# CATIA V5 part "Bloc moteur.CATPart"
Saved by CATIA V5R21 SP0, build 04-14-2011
Part number: bloc moteur
Material "Aluminium": density 2710 kg/m3, Young's modulus 7e+10 Pa, Poisson ratio 0.346, thermal expansion 2.36e-05 1/K
Bounding box of the stored display mesh (mm): x -34 to 34, y -31.5 to 37.5, z -15.714 to 54
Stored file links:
  C:\Users\Olivier\Desktop\redaction CATIA (local)\CATIA\DONNEES\Exercice mise en plan 2 (Pompe de ventilation)\Pompe de ventilation (Product inclus)\Bloc moteur.CATPart
  C:\Program Files\Dassault Systemes\B21\win_b64\startup\materials\French\Catalog.CATMaterial
  C:\Users\Olivier\Desktop\redaction CATIA (local)\CATIA\DONNEES\Exercice mise en plan 2 (Pompe de ventilation)\Pompe de ventilation (Product inclus)\CATIA_EnvironmentMap_Satin_512x512.jpg
  C:\Users\Olivier\Desktop\redaction CATIA (local)\pompe à moteur de ventilation refait\Pompe_a_moteur_de_ventilation.CATProduct
  C:\Users\Olivier\Desktop\redaction CATIA (local)\pompe à moteur de ventilation refait\Ecrou a collerette M5.CATPart
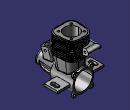
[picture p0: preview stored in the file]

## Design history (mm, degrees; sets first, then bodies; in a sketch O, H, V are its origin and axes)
Body1 (main body), material "Aluminium"
  Sketch1 on yz-plane, origin (0, 0, 0), H (0, 1, 0), V (0, 0, 1)
    line L1 (30, 0) -> (30, -15.5)
    line L2 (30, -15.5) -> (-3.0173, -15.5)
    line L3 (30, 0) -> (-30, 0)
    point P3 (-30, 0)
    line L4 (-30, -9) -> (-6, -11.039)
    point P4 (-30, -9)
    point P5 (-6, -11.039)
    line L5 (-6, -11.039) -> (-3.0173, -15.5)
    line L6 (-30, 0) -> (-30, -9)
    distance P3 P4 = 9
    distance P5 L1 = 36
    length L3 = 60
    length L1 = 15.5
    vertical: L1 V, L6 V
    horizontal: L2 H, L3 H
  Shaft1: profile Sketch1, axis Sketch1.L3, angle 360
  Plane1: type Offset, RefPlane xy-plane, Offset 54
  Sketch2 on Plane1, origin (0, 0, 54), H (1, 0, 0), V (0, 1, 0)
    point P1 (-15.991, -3)
    line L1 (-7.4607, -3) -> (7.4737, -3)
    line L2 (4.6271, 28) -> (-4.6217, 28)
    point P2 (16.009, -3)
    point P3 (14, 28)
    point P4 (-14, 28)
    reference projected line E1 (15.5, 30) -> (-15.5, 30) from edge [face of Shaft1 from Sketch1.L1 | face of Shaft1 from Sketch1.L2]
    line L3 (15.457, 5.5174) -> (14.6061, 18.6467)
    line L4 (-15.4443, 5.5128) -> (-14.6011, 18.6409)
    arc A1 centre (-7.4607, 5) radius 8 from (-7.4607, -3) to (-15.4443, 5.5128) cw
    arc A2 centre (7.4737, 5) radius 8 from (7.4737, -3) to (15.457, 5.5174) ccw
    arc A3 centre (4.6271, 18) radius 10 from (14.6061, 18.6467) to (4.6271, 28) ccw
    arc A4 centre (-4.6217, 18) radius 10 from (-4.6217, 28) to (-14.6011, 18.6409) ccw
    distance E1 L2 = 2
    distance P4 V = 14
    distance P1 P2 = 32
    radius A1 = 8
    radius A2 = 8
    distance P3 P4 = 28
    radius A3 = 10
    radius A4 = 10
    distance L1 L2 = 31
    horizontal: L2 H
    coincidence: L1 P1, L4 P1, L1 P2, L3 P2, L3 P3, L2 P3, L2 P4, L4 P4
    tangency: A1 L1, A1 L4, A2 L1, A2 L3, A3 L3, A3 L2, A4 L2, A4 L4
  Pad1: profile Sketch2, direction (0, 0, -1), length 27
  Sketch3 on end face of Pad1, origin (0, 0, 27), H (1, 0, 0), V (0, -1, 0)
  Sketch4 on end face of Pad1, origin (0, 0, 27), H (1, 0, 0), V (0, -1, 0)
    construction line L1 through (0, 0) direction (1, 0)
    construction line L2 through (0, 0) direction (0, 1)
  Sketch5 on end face of Pad1, origin (0, 0, 27), H (1, 0, 0), V (0, -1, 0)
    reference projected arc E1 centre (-4.6217, -18) radius 10 from (-14.6011, -18.6409) to (-4.6217, -28) ccw from edge [end face of Pad1 | face of Pad1 from Sketch2.A4]
    reference projected arc E2 centre (-7.4607, -5) radius 8 from (-7.4607, 3) to (-15.4443, -5.5128) ccw from edge [end face of Pad1 | face of Pad1 from Sketch2.A1]
    reference projected arc E3 centre (4.6271, -18) radius 10 from (4.6271, -28) to (14.6061, -18.6467) ccw from edge [end face of Pad1 | face of Pad1 from Sketch2.A3]
    line L1 (14.6061, -18.6467) -> (15.457, -5.5174)
    line L2 (7.4737, 3) -> (-7.4607, 3)
    line L3 (-15.4443, -5.5128) -> (-14.6011, -18.6409)
    line L4 (4.6271, -28) -> (-4.6217, -28)
    arc A1 centre (7.4737, -5) radius 8 from (7.4737, 3) to (15.457, -5.5174) cw
    arc A2 centre (4.6271, -18) radius 10 from (14.6061, -18.6467) to (4.6271, -28) cw
    arc A3 centre (-4.6217, -18) radius 10 from (-4.6217, -28) to (-14.6011, -18.6409) cw
    arc A4 centre (-7.4607, -5) radius 8 from (-15.4443, -5.5128) to (-7.4607, 3) cw
    tangency: L1 E3, L2 E2, L3 E1, L4 E1, A1 L1, A2 L4, A3 L3, A4 L2
  Sketch6 on xy-plane, origin (0, 0, 0), H (1, 0, 0), V (0, 1, 0)
    construction line L1 through (0, 0) direction (1, 0)
    construction line L2 through (0, 0) direction (0, 1)
    construction line L3 through (0, 0) direction (1, 0)
    construction line L4 through (0, 0) direction (0, 1)
    point P1 (0, 2.4613)
    construction line L5 through (0, 0) direction (1, 0)
    construction line L6 through (0, 0) direction (0, 1)
    point P2 (-12.8, 0.0613)
    point P3 (12.7992, 0.2685)
    point P4 (11.2, 24.8613)
    point P5 (-11.2, 24.8613)
    line L7 (-5.9184, 0.117) -> (6.0249, 0.2137)
    line L8 (3.7033, 24.8613) -> (-3.6995, 24.8613)
    line L9 (12.3596, 7.0288) -> (11.6864, 17.3804)
    line L10 (-12.3569, 6.9289) -> (-11.6829, 17.3764)
    arc A1 centre (-5.9702, 6.5168) radius 6.4 from (-5.9184, 0.117) to (-12.3569, 6.9289) cw
    arc A2 centre (5.9731, 6.6135) radius 6.4 from (6.0249, 0.2137) to (12.3596, 7.0288) ccw
    arc A3 centre (3.7033, 16.8613) radius 8 from (11.6864, 17.3804) to (3.7033, 24.8613) ccw
    arc A4 centre (-3.6995, 16.8613) radius 8 from (-3.6995, 24.8613) to (-11.6829, 17.3764) ccw
  Loft1: solid, Sections (Sketch5; Sketch6)
  Plane2: type Offset, RefPlane start face of Pad1, Offset 0.5
  Sketch7 on Plane2, origin (0, 0, 53.5), H (1, 0, 0), V (0, -1, 0)
    reference projected curve E1 from start face of Pad1
    construction line L1 through (0, 2.1) direction (1, 0)
    construction line L2 through (0, 2.1) direction (0, 1)
    point P1 (0, 3)
    point P2 (0, 1.25)
    construction line L3 through (0, 1.25) direction (1, 0)
    construction line L4 through (0, 1.25) direction (0, 1)
    point P3 (0, 4.55)
    point P4 (0, -12.5)
    line L5 (8.2211, 4.55) -> (-8.2068, 4.55)
    arc A1 centre (-8.2069, -4.2499) radius 8.7999 from (-8.2068, 4.55) to (-16.9887, -4.814) ccw
    line L6 (-16.9887, -4.814) -> (-16.0612, -19.255)
    arc A2 centre (-5.0839, -18.5501) radius 10.9999 from (-16.0612, -19.255) to (-5.0838, -29.55) ccw
    line L7 (-5.0838, -29.55) -> (5.0898, -29.55)
    arc A3 centre (5.0899, -18.5501) radius 10.9999 from (5.0898, -29.55) to (16.0668, -19.2614) ccw
    line L8 (16.0668, -19.2614) -> (17.0027, -4.8191)
    arc A4 centre (8.2212, -4.2499) radius 8.7999 from (17.0027, -4.8191) to (8.2211, 4.55) ccw
    coincidence: P1 E1, P1 L2
  Pad2: profile Sketch7, direction (0, 0, -1), length 1
  RectPattern1: of Pad2, direction 1 instances 12, spacing 2.2727, along axis of face of Pad1 from Sketch2.A3 reversed
  Sketch8 on start face of Pad1, origin (0, 0, 54), H (1, 0, 0), V (0, 1, 0)
    reference projected line E1 (4.6271, 28) -> (-4.6217, 28) from edge [face of Pad1 from Sketch2.L2 | start face of Pad1]
    point P2 (-4.6217, 28)
    point P3 (-7.4607, -3)
    reference projected line E4 (-14.6011, 18.6409) -> (-15.4443, 5.5128) from edge [face of Pad1 from Sketch2.L4 | start face of Pad1]
    point P7 (-14.6011, 18.6409)
    point P8 (-15.4443, 5.5128)
    circle A1 centre (-9.545, 22.045) radius 1.5
    point P9 (-9.545, 22.045)
    circle A2 centre (-9.545, 2.955) radius 1.5
    point P10 (-9.545, 2.955)
    point P11 (4.6217, 28)
    point P12 (7.4607, -3)
    point P13 (15.4443, 5.5128)
    point P14 (14.6011, 18.6409)
    point P15 (9.545, 22.045)
    circle A3 centre (9.545, 22.045) radius 1.5
    circle A4 centre (9.545, 2.955) radius 1.5
    construction line L1 (14.6011, 18.6409) -> (15.4443, 5.5128)
    circle A5 centre (0, 12.5) radius 10.5
    point P17 (0, 12.5)
    point P18 (0.0027, 28)
    distance P9 P10 = 19.09
    distance P10 V = 9.545
    distance P9 V = 9.545
    distance P15 P17 V = 9.545
    symmetry: P2 P11 V, P3 P12 V, P8 P13 V, P7 P14 V, E4 L1 V, A1 A3 V, A2 A4 V
    coincidence: P17 V
    midpoint: P18 E1
  MultiPocket1: profile Sketch8, domains (length 54; length 8; length 8; length 8; length 8)
  Sketch9 on face of Shaft1 from Sketch1.L1, origin (0, 30, 0), H (-1, 0, 0), V (0, 0, 1)
    circle A1 centre (0, 0) radius 13.25
    circle A2 centre (0, 0) radius 8
  MultiPocket2: profile Sketch9, domains (length 66; length 30)
  Plane3: type Angle, RefPlane face of RectPattern1, Direction edge [face of RectPattern1 | face of RectPattern1], Angle 71
  Sketch10 on Plane3, origin (0.1039, -12.2988, 24.8319), H (-1, -0.0077, -0.0027), V (-0.0082, 0.9455, 0.3256)
    point P1 (0, -8.2811)
    line L1 (7.25, -3.0311) -> (7.25, -13.5311)
    line L2 (5.25, -15.5311) -> (-5.25, -15.5311)
    line L3 (-7.25, -13.5311) -> (-7.25, -3.0311)
    line L4 (-5.25, -1.0311) -> (5.25, -1.0311)
    point P2 (7.25, -15.5311)
    point P3 (-7.25, -15.5311)
    point P4 (-7.25, -1.0311)
    arc A1 centre (-5.25, -3.0311) radius 2 from (-7.25, -3.0311) to (-5.25, -1.0311) cw
    arc A2 centre (5.25, -3.0311) radius 2 from (5.25, -1.0311) to (7.25, -3.0311) cw
    arc A3 centre (5.25, -13.5311) radius 2 from (7.25, -13.5311) to (5.25, -15.5311) cw
    arc A4 centre (-5.25, -13.5311) radius 2 from (-5.25, -15.5311) to (-7.25, -13.5311) cw
    distance P3 P4 = 14.5
    radius A1 = 2
    radius A2 = 2
    distance P2 P3 = 14.5
    radius A3 = 2
    radius A4 = 2
    coincidence: P1 V, L3 P4, L4 P4, L1 P2, L2 P2, L2 P3, L3 P3
    vertical: L1 V, L3 V
    horizontal: L2 H, L4 H
    equidistance: L1 L3 P1, L2 L4 P1
    tangency: A1 L3, A1 L4, A2 L4, A2 L1, A3 L1, A3 L2, A4 L2, A4 L3
  Pad3: profile Sketch10, direction (0, 0.3256, -0.9455), up to the existing solid (limit type 2)
  Sketch11 on start face of Pad3, origin (0.0962, -11.4101, 25.1379), H (1, 0.0077, 0.0027), V (-0.0082, 0.9455, 0.3256)
    circle A1 centre (0, -9.2211) radius 5
    point P1 (0, -9.2211)
    reference projected line E1 (-5.25, -1.9711) -> (5.25, -1.9711) from edge [start face of Pad3 | face of Pad3 from Sketch10.L4]
    distance P1 E1 = 7.25
    coincidence: P1 V
  Pocket1: profile Sketch11, direction (0, 0.3256, -0.9455), through (limit type 6)
  Fillet1: radius 1, on edge [face of Shaft1 from Sketch1.L2 | face of Loft1]; edge [face of Shaft1 from Sketch1.L4 | face of Pad3 from Sketch10.L3]
  Sketch12 on yz-plane, origin (0, 0, 0), H (0, 1, 0), V (0, 0, 1)
    axis line L1 (-14.7367, 0) -> (16.2843, 0)
    point P1 (-14.7367, 0)
    coincidence: P1 H
    horizontal: L1 H
  Plane4: type Angle, RefPlane yz-plane, Direction Sketch12.H, Angle 10
  Sketch13 on Plane4, origin (0, 0, 0), H (0, 1, 0), V (0.1736, 0, 0.9848)
    arc A1 centre (-5.3078, 36.1588) radius 50 from (-3.7677, -13.8175) to (-26.6567, -9.0544) cw
  Stiffener1: ExtendedProfile Sketch13, ThicknessTop 0, ThicknessValue 2
  Plane5: type Angle, RefPlane yz-plane, Direction Sketch12.H, Angle -10
  Sketch14 on Plane5, origin (0, 0, 0), H (0, 1, 0), V (-0.1736, 0, 0.9848)
    arc A1 centre (-5.3078, 36.1588) radius 50 from (-3.7677, -13.8175) to (-26.6567, -9.0544) cw
  Stiffener2: ExtendedProfile Sketch14, ThicknessTop 0, ThicknessValue 2
  CircPattern1: of Stiffener1, Stiffener2, instances 2, angular step 90, axis from face of Shaft1 from Sketch1.L4
  CircPattern2: of Stiffener1, Stiffener2, instances 2, angular step 90, axis from face of Shaft1 from Sketch1.L4
  Sketch15 on yz-plane, origin (0, 0, 0), H (0, 1, 0), V (0, 0, 1)
    construction line L1 (-7.6243, 24.8244) -> (-26.5044, 17.0975)
    point P3 (-12.515, 22.8228)
    coincidence: P3 L1
  Sketch16 on face of Shaft1 from Sketch1.L1, origin (0, 30, 0), H (-1, 0, 0), V (0, 0, 1)
    circle A1 centre (12.7279, 12.7279) radius 1.5
    arc A2 centre (12.7279, 12.7279) radius 3 from (15.2181, 11.0549) to (11.0549, 15.2181) ccw
    line L1 (15.2181, 11.0549) -> (13.5624, 7.5041)
    point P2 (15.2181, 11.0549)
    point P3 (13.5624, 7.5041)
    point P4 (7.5041, 13.5624)
    point P5 (11.0549, 15.2181)
    line L2 (11.0549, 15.2181) -> (7.5041, 13.5624)
    point P7 (-15.2181, 11.0549)
    point P8 (-13.5624, 7.5041)
    point P9 (-7.5041, 13.5624)
    point P10 (-11.0549, 15.2181)
    circle A3 centre (-12.7279, 12.7279) radius 1.5
    arc A4 centre (-12.7279, 12.7279) radius 3 from (-15.2181, 11.0549) to (-11.0549, 15.2181) cw
    line L3 (-15.2181, 11.0549) -> (-13.5624, 7.5041)
    line L4 (-11.0549, 15.2181) -> (-7.5041, 13.5624)
    point P12 (15.2181, -11.0549)
    point P13 (13.5624, -7.5041)
    point P14 (7.5041, -13.5624)
    point P15 (11.0549, -15.2181)
    point P17 (-15.2181, -11.0549)
    point P18 (-13.5624, -7.5041)
    point P19 (-7.5041, -13.5624)
    point P20 (-11.0549, -15.2181)
    circle A5 centre (12.7279, -12.7279) radius 1.5
    arc A6 centre (12.7279, -12.7279) radius 3 from (15.2181, -11.0549) to (11.0549, -15.2181) cw
    line L5 (15.2181, -11.0549) -> (13.5624, -7.5041)
    line L6 (11.0549, -15.2181) -> (7.5041, -13.5624)
    circle A7 centre (-12.7279, -12.7279) radius 1.5
    arc A8 centre (-12.7279, -12.7279) radius 3 from (-15.2181, -11.0549) to (-11.0549, -15.2181) ccw
    line L7 (-15.2181, -11.0549) -> (-13.5624, -7.5041)
    line L8 (-11.0549, -15.2181) -> (-7.5041, -13.5624)
    projected circle E1 centre (0, 0) radius 15.5 from edge [face of Shaft1 from Sketch1.L1 | face of Shaft1 from Sketch1.L2]
    projected arc E2 centre (0, 0) radius 15.5 from (-7.5041, 13.5624) to (-13.5624, 7.5041) ccw from edge [face of Shaft1 from Sketch1.L1 | face of Shaft1 from Sketch1.L2]
    projected arc E3 centre (0, 0) radius 15.5 from (-13.5624, -7.5041) to (-7.5041, -13.5624) ccw from edge [face of Shaft1 from Sketch1.L1 | face of Shaft1 from Sketch1.L2]
    projected arc E4 centre (0, 0) radius 15.5 from (7.5041, -13.5624) to (13.5624, -7.5041) ccw from edge [face of Shaft1 from Sketch1.L1 | face of Shaft1 from Sketch1.L2]
    projected arc E5 centre (0, 0) radius 15.5 from (13.5624, 7.5041) to (7.5041, 13.5624) ccw from edge [face of Shaft1 from Sketch1.L1 | face of Shaft1 from Sketch1.L2]
    radius A2 = 3
    symmetry: P2 P7 V, P3 P8 V, P4 P9 V, P5 P10 V, A1 A3 V, A2 A4 V, L1 L3 V, L2 L4 V, P2 P12 H, P3 P13 H, P4 P14 H, P5 P15 H, P7 P17 H, P8 P18 H, P9 P19 H, P10 P20 H, A1 A5 H, A2 A6 H, L1 L5 H, L2 L6 H, A3 A7 H, A4 A8 H, L3 L7 H, L4 L8 H
  Pad4: profile Sketch16, direction (0, -1, 0), length 2
  Sketch17 on yz-plane, origin (0, 0, 0), H (0, 1, 0), V (0, 0, 1)
    reference projected line E1 through (-11.1809, -3.8499) direction (-0.3256, 0.9455) from axis of face of Pocket1 from Sketch11.A1
    circle A1 centre (-18.5006, 17.4083) radius 1.5
    point P3 (-18.5006, 17.4083)
    reference projected line E2 (-15.1086, 23.8644) -> (-25.0362, 20.446) from edge [start face of Pad3 | face of Pad3 from Sketch10.L3]
    distance P3 E2 = 5
    coincidence: P3 E1
  Pocket2: profile Sketch17, direction (-1, 0, 0), length 9, mirrored extent
  Plane6: type Offset, RefPlane Plane1, Offset 16.5, reversed
  Sketch18 on Plane6, origin (0, 0, 37.5), H (1, 0, 0), V (0, 1, 0)
    projected arc E1 centre (-7.4607, 5) radius 8 from (-15.4443, 5.5128) to (-7.4607, -3) ccw from edge [face of Pad1 from Sketch2.A1 | start face of Pad1]
    point P2 (-7.4607, -3)
    projected line E2 (-7.4607, -3) -> (7.4737, -3) from edge [face of Pad1 from Sketch2.L1 | start face of Pad1]
    projected line E3 (-7.4607, -3) -> (0.0065, -3) from edge [face of Pad1 from Sketch2.L1 | start face of Pad1]
    point P3 (-7.4607, -3)
    projected line E4 (4.6271, 28) -> (-4.6217, 28) from edge [face of Pad1 from Sketch2.L2 | start face of Pad1]
    projected line E5 (0.0027, 28) -> (-4.6217, 28) from edge [face of Pad1 from Sketch2.L2 | start face of Pad1]
    point P6 (-4.6217, 28)
    projected arc E6 centre (-4.6217, 18) radius 10 from (-4.6217, 28) to (-14.6011, 18.6409) ccw from edge [face of Pad1 from Sketch2.A4 | start face of Pad1]
    point P7 (-4.6217, 28)
    projected line E7 (-14.6011, 18.6409) -> (-15.4443, 5.5128) from edge [face of Pad1 from Sketch2.L4 | start face of Pad1]
    line L1 (0.0065, -3) -> (0.0065, -12.5)
    point P11 (0.0065, -3)
    line L2 (0.0065, -12.5) -> (-18.5, -12.5)
    line L3 (-18.5, -12.5) -> (-18.5, 37.5)
    line L4 (-18.5, 37.5) -> (0, 37.5)
    point P15 (0, 37.5)
    line L5 (0, 37.5) -> (0.0027, 28)
    point P16 (0.0027, 28)
    point P17 (0.0046, 12.5)
    distance L2 L4 = 50
    length L4 = 18.5
    midpoint: P11 E2, P16 E4
    vertical: L1 V, L3 V
    horizontal: L2 H, L4 H
    coincidence: P15 V, P2 P3, P6 P7
  Pad5: profile Sketch18, direction (0, 0, 1), length 4.5, mirrored extent
  Sketch19 on face of Pad5 from Sketch18.L5, origin (0.0107, 0, 0), H (-0.0003, 1, 0), V (0, 0, 1)
    circle A1 centre (32.5355, 37.5) radius 1.5
    point P1 (32.5355, 37.5)
    reference projected line E1 (28, 42) -> (37.5, 42) from edge [face of Pad5 from Sketch18.L5 | end face of Pad5]
    reference projected line E2 (37.5, 33) -> (37.5, 42) from edge [face of Pad5 from Sketch18.L4 | face of Pad5 from Sketch18.L5]
    reference projected line E3 (-12.5, 33) -> (-12.5, 42) from edge [face of Pad5 from Sketch18.L1 | face of Pad5 from Sketch18.L2]
    point P2 (37.5, 37.5)
    circle A2 centre (-7.5355, 37.5) radius 1.5
    distance P1 E1 = 4.5
    distance E2 E3 = 50 (reference)
  Pocket3: profile Sketch19, direction (-1, -0.0003, 0), length 8
  Fillet2: radius 4.5, on edge [face of Pad5 from Sketch18.L4 | end face of Pad5]; edge [face of Pad5 from Sketch18.L3 | end face of Pad5]; edge [start face of Pad5 | face of Pad5 from Sketch18.L4]; edge [face of Pad5 from Sketch18.L2 | end face of Pad5]; edge [start face of Pad5 | face of Pad5 from Sketch18.L2]; edge [start face of Pad5 | face of Pad5 from Sketch18.L3]
  Sketch20 on xy-plane, origin (0, 0, 0), H (1, 0, 0), V (0, 1, 0)
    line L1 (13.8085, 26.419) -> (34, 26.419)
    line L2 (34, 26.419) -> (34, 6.419)
    line L3 (34, 6.419) -> (13.7241, 6.419)
    distance L2 V = 34
    length L2 = 20
    horizontal: L1 H, L3 H
    vertical: L2 V
  Stiffener3: ExtendedProfile Sketch20, ThicknessTop 0, ThicknessValue 3.206
  Mirror1: of Stiffener3, about yz-plane
  Sketch21 on face of Stiffener3, origin (0, 0, 1.603), H (1, 0, 0), V (0, 1, 0)
    construction line L1 (28, 19.419) -> (28, 13.419)
    line L2 (31, 19.419) -> (31, 13.419)
    line L3 (25, 13.419) -> (25, 19.419)
    arc A1 centre (28, 13.419) radius 3 from (31, 13.419) to (25, 13.419) cw
    arc A2 centre (28, 19.419) radius 3 from (25, 19.419) to (31, 19.419) cw
    point P3 (31, 19.419)
    point P4 (31, 13.419)
    point P5 (25, 13.419)
    point P6 (25, 19.419)
    point P7 (28, 16.419)
    reference projected line E1 (15.4169, 26.419) -> (34.18, 26.419) from edge [face of Stiffener3 | face of Stiffener3 from Sketch20.L1]
    construction line L4 (-28, 19.419) -> (-28, 13.419)
    point P10 (-31, 19.419)
    point P11 (-31, 13.419)
    point P12 (-25, 13.419)
    point P13 (-25, 19.419)
    point P14 (-28, 16.419)
    line L5 (-31, 19.419) -> (-31, 13.419)
    line L6 (-25, 13.419) -> (-25, 19.419)
    arc A3 centre (-28, 13.419) radius 3 from (-31, 13.419) to (-25, 13.419) ccw
    arc A4 centre (-28, 19.419) radius 3 from (-25, 19.419) to (-31, 19.419) ccw
    distance L1 L2 = 3
    length L1 = 6
    distance P7 E1 = 10
    distance L1 L4 = 56
    vertical: L1 V
    tangency: A1 L2, A2 L2, A1 L3, A2 L3
    midpoint: P7 L1
    symmetry: L1 L4 V, P3 P10 V, P4 P11 V, P5 P12 V, P6 P13 V, P7 P14 V, L2 L5 V, L3 L6 V, A1 A3 V, A2 A4 V
  Pocket4: profile Sketch21, direction (0, 0, -1), length 8
  Plane7: type Offset, RefPlane xy-plane, Offset 54
  Sketch22 on face of Shaft1 from Sketch1.L6, origin (0, -30, 0), H (1, 0, 0), V (0, 0, 1)
    projected circle E1 centre (0, 0) radius 9 from edge [face of Shaft1 from Sketch1.L4 | face of Shaft1 from Sketch1.L6]
    projected circle E2 centre (0, 0) radius 8 from edge [face of Shaft1 from Sketch1.L6 | face of MultiPocket2 from Sketch9.A2]
  Pad6: profile Sketch22, direction (0, -1, 0), length 1.5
